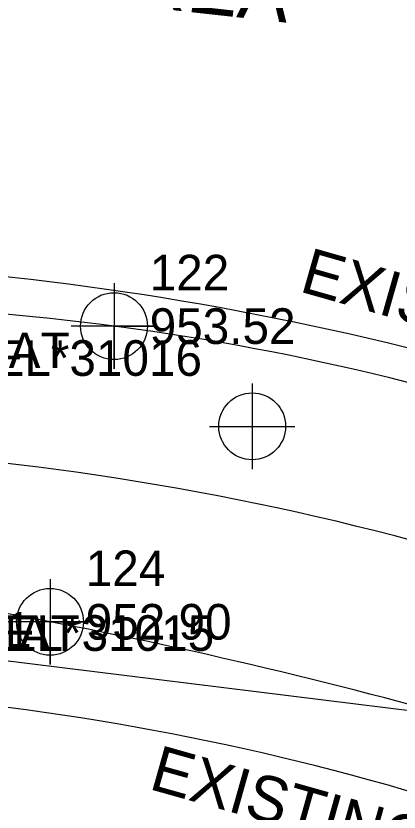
# Model space of a CAD drawing. Extents: x 1150279 to 1151282, y 654632 to 657999.
# Drawn here: x 1150817.2 to 1150844, y 657109.7 to 657165.5 of the extents above; entities that cross this region are included whole.
import ezdxf

# ---------------------------------------------------------------- set-up
doc = ezdxf.new("R2010")
doc.units = 0
for name, color, linetype in [('COGO Default Chain', 7, 'Continuous'), ('COGO Default Curve', 7, 'Continuous'), ('Cogo Default Point CELL', 7, 'Continuous'), ('Default Symbol Cogo Comment', 7, 'Continuous'), ('Exist Horizontal Alignment', 7, 'Continuous'), ('Exist Right of Way Line', 7, 'Continuous'), ('Exist Right of Way Line Text', 7, 'Continuous'), ('Exist Roads EOP', 7, 'Continuous'), ('Exist Roads EOP Cogo Comment', 7, 'Continuous'), ('Exist Roads EOP Cogo Elevation', 7, 'Continuous'), ('Exist Roads EOP Cogo Number', 7, 'Continuous'), ('Exist Roads EOP Cogo Point CELL', 7, 'Continuous'), ('Exist Roads EOP Text', 7, 'Continuous'), ('Exist Structure Major Bridge Seam Cogo Comment', 7, 'Continuous')]:
    doc.layers.add(name, color=color, linetype=linetype)

msp = doc.modelspace()

# ---------------------------------------------------------------- linework, layer by layer
at = {"layer": 'COGO Default Chain'}
msp.add_line((1150614.756, 657145.261), (1150931.292, 657106.062), dxfattribs=at)
msp.add_arc((1150793.42, 656935.454), 200, 65.68044, 91.66254, dxfattribs=at)
at = {"layer": 'COGO Default Curve'}
msp.add_arc((1150793.42, 656935.454), 200, 65.68044, 91.66254, dxfattribs=at)
at = {"layer": 'Cogo Default Point CELL'}
for points in [[(1150833.739, 657139.708), (1150833.739, 657136.708)], [(1150830.739, 657136.708), (1150833.739, 657136.708)], [(1150833.739, 657136.708), (1150836.739, 657136.708)], [(1150833.739, 657136.708), (1150833.739, 657133.708)]]:
    msp.add_lwpolyline(points, dxfattribs=at)
msp.add_circle((1150833.739, 657136.708), 2.344, dxfattribs=at)
at = {"layer": 'Exist Horizontal Alignment'}
msp.add_arc((1150793.42, 656935.454), 200, 65.68044, 91.66254, dxfattribs=at)
at = {"layer": 'Exist Right of Way Line'}
for radius, end in [(213, 88.72471), (183, 91.66254)]:
    msp.add_arc((1150793.42, 656935.454), radius, 65.68044, end, dxfattribs=at)
at = {"layer": 'Exist Roads EOP'}
for centre, major_axis, ratio, start_param, end_param in [((1150800.442, 656964.8), (-177.198, 34.758), 0.999524, 4.48455, 4.91412), ((1150752.571, 656773.823), (-278.809, 220.877), 0.99945, 5.05593, 5.247845)]:
    msp.add_ellipse(centre, major_axis=major_axis, ratio=ratio, start_param=start_param, end_param=end_param, dxfattribs=at)
at = {"layer": 'Exist Roads EOP Cogo Point CELL'}
for points in [[(1150824.051, 657146.739), (1150824.051, 657140.739), (1150824.051, 657143.739), (1150827.051, 657143.739), (1150821.051, 657143.739)], [(1150819.568, 657125.998), (1150819.568, 657119.998), (1150819.568, 657122.998), (1150822.568, 657122.998), (1150816.568, 657122.998)]]:
    msp.add_lwpolyline(points, dxfattribs=at)
for centre in [(1150824.051, 657143.739), (1150819.568, 657122.998)]:
    msp.add_circle(centre, 2.344, dxfattribs=at)

# ---------------------------------------------------------------- texts
at = {"layer": 'Default Symbol Cogo Comment'}
for p in [(1150799.389, 657140.789), (1150800.09, 657120.96)]:
    msp.add_text('BRIDGESEAT', height=2.5, dxfattribs=at).set_placement(p)
at = {"layer": 'Exist Right of Way Line Text'}
for rotation, p in [(344.0874, (1150836.967, 657146.19)), (344.2739, (1150826.415, 657111.293))]:
    msp.add_text('EXISTING R/W', height=3.2, rotation=rotation, dxfattribs=at).set_placement(p)
at = {"layer": 'Exist Roads EOP Cogo Comment'}
msp.add_text('OC*30011', height=2.5, dxfattribs=at).set_placement((1150802.671, 657121.176))
at = {"layer": 'Exist Roads EOP Cogo Elevation'}
for s, p in [('953.52', (1150826.551, 657142.489)), ('952.90', (1150822.068, 657121.748))]:
    msp.add_text(s, height=2.5, dxfattribs=at).set_placement(p)
at = {"layer": 'Exist Roads EOP Cogo Number'}
for s, p in [('122', (1150826.551, 657146.239)), ('124', (1150822.068, 657125.498))]:
    msp.add_text(s, height=2.5, dxfattribs=at).set_placement(p)
at = {"layer": 'Exist Roads EOP Text'}
msp.add_text('AREA', height=4, rotation=353.6867, dxfattribs=at).set_placement((1150821.668, 657166.62))
at = {"layer": 'Exist Structure Major Bridge Seam Cogo Comment'}
for s, p in [('BL*31034 EL*31016', (1150799.919, 657140.249)), ('EL*31034 EL*31015', (1150800.772, 657120.958))]:
    msp.add_text(s, height=2.5, dxfattribs=at).set_placement(p)

doc.saveas('drawing.dxf')
